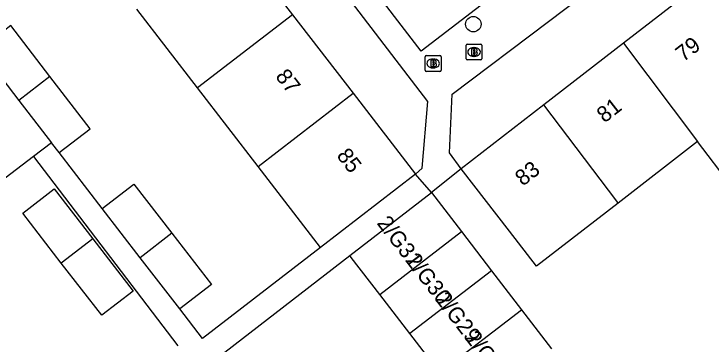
# Model space of a CAD drawing. Extents: x 159222 to 160346, y 381249 to 382166.
# Drawn here: x 159664.75 to 159708.81, y 381473.76 to 381494.62 of the extents above; entities that cross this region are included whole.
import ezdxf

# ---------------------------------------------------------------- set-up
doc = ezdxf.new("R2010")
doc.units = 0
for name, color, linetype in [('IMGEO_Boom', 7, 'Continuous'), ('IMGEO_Brandkraan', 7, 'Continuous'), ('IMGEO_Pand', 7, 'Continuous'), ('IMGEO_Pand_nummerreeks', 7, 'Continuous'), ('IMGEO_Voetpad_open', 7, 'Continuous')]:
    doc.layers.add(name, color=color, linetype=linetype)

msp = doc.modelspace()

# ---------------------------------------------------------------- linework, layer by layer
at = {"layer": 'IMGEO_Boom'}
msp.add_circle((159693.788, 381493.977), 0.489, dxfattribs=at)
at = {"layer": 'IMGEO_Brandkraan'}
for p, q in [((159693.331, 381491.796), (159693.331, 381492.648)), ((159693.406, 381492.722), (159694.258, 381492.722)), ((159693.819, 381492.502), (159693.844, 381492.502)), ((159694.332, 381492.648), (159694.332, 381491.796)), ((159690.823, 381491.995), (159691.675, 381491.995)), ((159690.748, 381491.069), (159690.748, 381491.921)), ((159691.236, 381491.775), (159691.261, 381491.775)), ((159691.749, 381491.921), (159691.749, 381491.069)), ((159694.258, 381491.722), (159693.406, 381491.722)), ((159693.842, 381491.942), (159693.817, 381491.942)), ((159691.259, 381491.215), (159691.234, 381491.215)), ((159691.675, 381490.995), (159690.823, 381490.995))]:
    msp.add_line(p, q, dxfattribs=at)
for points in [[(159693.331, 381491.796), (159693.331, 381492.648)], [(159693.406, 381492.722), (159694.258, 381492.722)], [(159694.332, 381492.648), (159694.332, 381491.796)], [(159690.823, 381491.995), (159691.675, 381491.995)], [(159693.679, 381492.422), (159693.679, 381492.022), (159693.892, 381492.022)], [(159693.91, 381492.422), (159693.679, 381492.422)], [(159693.858, 381492.341), (159693.804, 381492.341), (159693.804, 381492.265)], [(159693.804, 381492.265), (159693.857, 381492.265)], [(159693.866, 381492.189), (159693.804, 381492.189), (159693.804, 381492.108)], [(159693.804, 381492.108), (159693.866, 381492.108)], [(159690.748, 381491.069), (159690.748, 381491.921)], [(159691.096, 381491.695), (159691.096, 381491.295), (159691.309, 381491.295)], [(159691.327, 381491.695), (159691.096, 381491.695)], [(159691.275, 381491.614), (159691.221, 381491.614), (159691.221, 381491.538)], [(159691.749, 381491.921), (159691.749, 381491.069)], [(159694.258, 381491.722), (159693.406, 381491.722)], [(159691.221, 381491.538), (159691.274, 381491.538)], [(159691.283, 381491.462), (159691.221, 381491.462), (159691.221, 381491.381)], [(159691.221, 381491.381), (159691.283, 381491.381)], [(159691.675, 381490.995), (159690.823, 381490.995)]]:
    msp.add_lwpolyline(points, dxfattribs=at)
for centre, radius, start, end in [((159693.408, 381492.646), 0.0765, 91.552, 178.448), ((159693.408, 381492.646), 0.0765, 91.552, 178.448), ((159694.256, 381492.646), 0.0765, 1.552, 88.448), ((159694.256, 381492.646), 0.0765, 1.552, 88.448), ((159690.825, 381491.919), 0.0765, 91.552, 178.448), ((159690.825, 381491.919), 0.0765, 91.552, 178.448), ((159691.673, 381491.919), 0.0765, 1.552, 88.448), ((159691.673, 381491.919), 0.0765, 1.552, 88.448), ((159693.859, 381492.303), 0.0379, 267.8285, 90.9355), ((159693.867, 381492.148), 0.0404, 269.8759, 90.5077), ((159693.898, 381492.273), 0.251, 268.6676, 293.5347), ((159693.914, 381492.277), 0.145, 59.4692, 91.5367), ((159693.939, 381492.324), 0.0922, 285.5137, 58.1501), ((159693.944, 381492.132), 0.105, 301.3115, 78.989), ((159691.276, 381491.576), 0.0379, 267.8285, 90.9355), ((159691.331, 381491.55), 0.145, 59.4692, 91.5367), ((159691.356, 381491.597), 0.0922, 285.5137, 58.1501), ((159693.408, 381491.798), 0.0765, 181.552, 268.448), ((159693.408, 381491.798), 0.0765, 181.552, 268.448), ((159694.256, 381491.798), 0.0765, 271.552, 358.448), ((159694.256, 381491.798), 0.0765, 271.552, 358.448), ((159691.284, 381491.421), 0.0404, 269.8759, 90.5077), ((159691.315, 381491.546), 0.251, 268.6676, 293.5347), ((159691.361, 381491.405), 0.105, 301.3115, 78.989), ((159690.825, 381491.071), 0.0765, 181.552, 268.448), ((159690.825, 381491.071), 0.0765, 181.552, 268.448), ((159691.673, 381491.071), 0.0765, 271.552, 358.448), ((159691.673, 381491.071), 0.0765, 271.552, 358.448)]:
    msp.add_arc(centre, radius, start, end, dxfattribs=at)
for centre, major_axis, ratio, start_param, end_param in [((159693.818, 381492.222), (-0.387, 0.002), 0.722429, 4.712389, 7.853982), ((159693.843, 381492.222), (-0.39, 0.002), 0.717154, 1.570796, 4.712389), ((159691.235, 381491.495), (-0.387, 0.002), 0.722429, 4.712389, 7.853982), ((159691.26, 381491.495), (-0.39, 0.002), 0.717154, 1.570796, 4.712389)]:
    msp.add_ellipse(centre, major_axis=major_axis, ratio=ratio, start_param=start_param, end_param=end_param, dxfattribs=at)
at = {"layer": 'IMGEO_Pand'}
for points in [[(159678.511, 381499.554), (159682.356, 381494.579)], [(159708.242, 381496.623), (159703.275, 381492.778)], [(159676.351, 381489.945), (159672.516, 381494.92)], [(159682.356, 381494.579), (159676.351, 381489.945)], [(159682.356, 381494.579), (159686.19, 381489.618)], [(159667.025, 381490.675), (159664.552, 381493.892), (159662.59, 381492.384)], [(159703.275, 381492.778), (159698.244, 381488.883)], [(159703.275, 381492.778), (159707.965, 381486.57)], [(159662.897, 381491.984), (159665.066, 381489.161)], [(159667.025, 381490.675), (159665.066, 381489.161)], [(159667.601, 381485.863), (159669.564, 381487.371), (159667.025, 381490.675)], [(159680.182, 381484.974), (159676.351, 381489.945)], [(159680.182, 381484.974), (159686.19, 381489.618)], [(159686.19, 381489.618), (159690.14, 381484.508)], [(159665.066, 381489.161), (159667.129, 381486.477)], [(159717.107, 381489.155), (159715.163, 381487.686), (159710.045, 381483.819), (159707.965, 381486.57)], [(159698.244, 381488.883), (159693.022, 381484.841)], [(159702.934, 381482.675), (159702.848, 381482.789), (159698.244, 381488.883)], [(159667.129, 381486.477), (159665.99, 381485.608)], [(159667.601, 381485.863), (159667.129, 381486.477)], [(159707.965, 381486.57), (159702.934, 381482.675)], [(159665.99, 381485.608), (159657.568, 381479.184)], [(159684.127, 381479.856), (159680.182, 381484.974)], [(159690.14, 381484.508), (159684.127, 381479.856)], [(159702.934, 381482.675), (159697.786, 381478.69), (159696.084, 381480.888), (159693.022, 381484.841)], [(159670.325, 381482.319), (159672.324, 381483.868), (159674.731, 381480.761)], [(159667.745, 381478.879), (159665.309, 381482.025), (159667.293, 381483.562), (159669.73, 381480.416)], [(159685.977, 381479.367), (159691.141, 381483.338)], [(159691.141, 381483.338), (159693.04, 381480.868)], [(159672.73, 381479.214), (159670.325, 381482.319)], [(159674.731, 381480.761), (159672.73, 381479.214)], [(159674.731, 381480.761), (159677.234, 381477.529), (159675.235, 381475.98)], [(159687.876, 381476.897), (159693.04, 381480.868)], [(159693.04, 381480.868), (159694.94, 381478.398)], [(159669.73, 381480.416), (159672.288, 381477.114), (159670.303, 381475.577), (159667.745, 381478.879)], [(159669.73, 381480.416), (159667.745, 381478.879)], [(159675.235, 381475.98), (159672.73, 381479.214)], [(159687.876, 381476.897), (159686.075, 381479.24), (159685.977, 381479.367)], [(159694.94, 381478.398), (159689.776, 381474.427)], [(159694.94, 381478.398), (159696.839, 381475.928)], [(159689.776, 381474.427), (159687.876, 381476.897)], [(159691.675, 381471.957), (159696.839, 381475.928)], [(159696.839, 381475.928), (159698.738, 381473.458)], [(159691.675, 381471.957), (159689.776, 381474.427)]]:
    msp.add_lwpolyline(points, dxfattribs=at)
at = {"layer": 'IMGEO_Voetpad_open'}
for points in [[(159690.14, 381484.508), (159690.551, 381484.871), (159690.909, 381489.081), (159684.573, 381497.389), (159684.25, 381498.359), (159684.259, 381500), (159684.268, 381501.76), (159683.984, 381502.536), (159662.423, 381530.546)], [(159697.998, 381505.616), (159701.706, 381500.913), (159700.521, 381500), (159696.449, 381496.864), (159690.486, 381492.27), (159686.844, 381497.036)], [(159693.022, 381484.841), (159692.285, 381485.843), (159692.448, 381489.553), (159698.537, 381494.153), (159703.622, 381497.995), (159707.889, 381497.097), (159708.242, 381496.623)], [(159670.325, 381482.319), (159667.601, 381485.863)], [(159665.99, 381485.608), (159675.115, 381473.645)], [(159691.141, 381483.338), (159690.14, 381484.508)], [(159693.022, 381484.841), (159691.141, 381483.338)], [(159684.127, 381479.856), (159676.672, 381474.115), (159675.235, 381475.98)], [(159696.363, 381448.545), (159677.614, 381472.891), (159685.977, 381479.367)]]:
    msp.add_lwpolyline(points, dxfattribs=at)

# ---------------------------------------------------------------- texts
at = {"layer": 'IMGEO_Pand_nummerreeks'}
for s, rotation, p in [('79', 37.7465, (159707.06, 381491.56)), ('87', 307.7008, (159681.237, 381490.663)), ('81', 37.7439, (159702.076, 381487.702)), ('85', 307.7008, (159685.105, 381485.658)), ('83', 37.7439, (159696.913, 381483.705)), ('2/G31', 307.4879, (159687.652, 381481.394)), ('2/G30', 307.4879, (159689.464, 381479.031)), ('2/G29', 307.4879, (159691.338, 381476.588)), ('2/G28', 307.4879, (159693.219, 381474.136))]:
    msp.add_text(s, height=1, rotation=rotation, dxfattribs=at).set_placement(p)

doc.saveas('drawing.dxf')
